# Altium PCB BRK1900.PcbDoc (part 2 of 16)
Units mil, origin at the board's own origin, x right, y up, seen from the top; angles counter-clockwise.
Board outline 8858.27 x 5905.51 mil, 10 copper layers (L1-TOP, L2-GND, L3-PWR, L4-GND, L5-PWR, L6-PWR, L7-GND, L8-SIG, L9-GND, L10-BOT), stack 48.824 mil thick; 456 components, 571 nets, 2296 pads, 2416 vias.
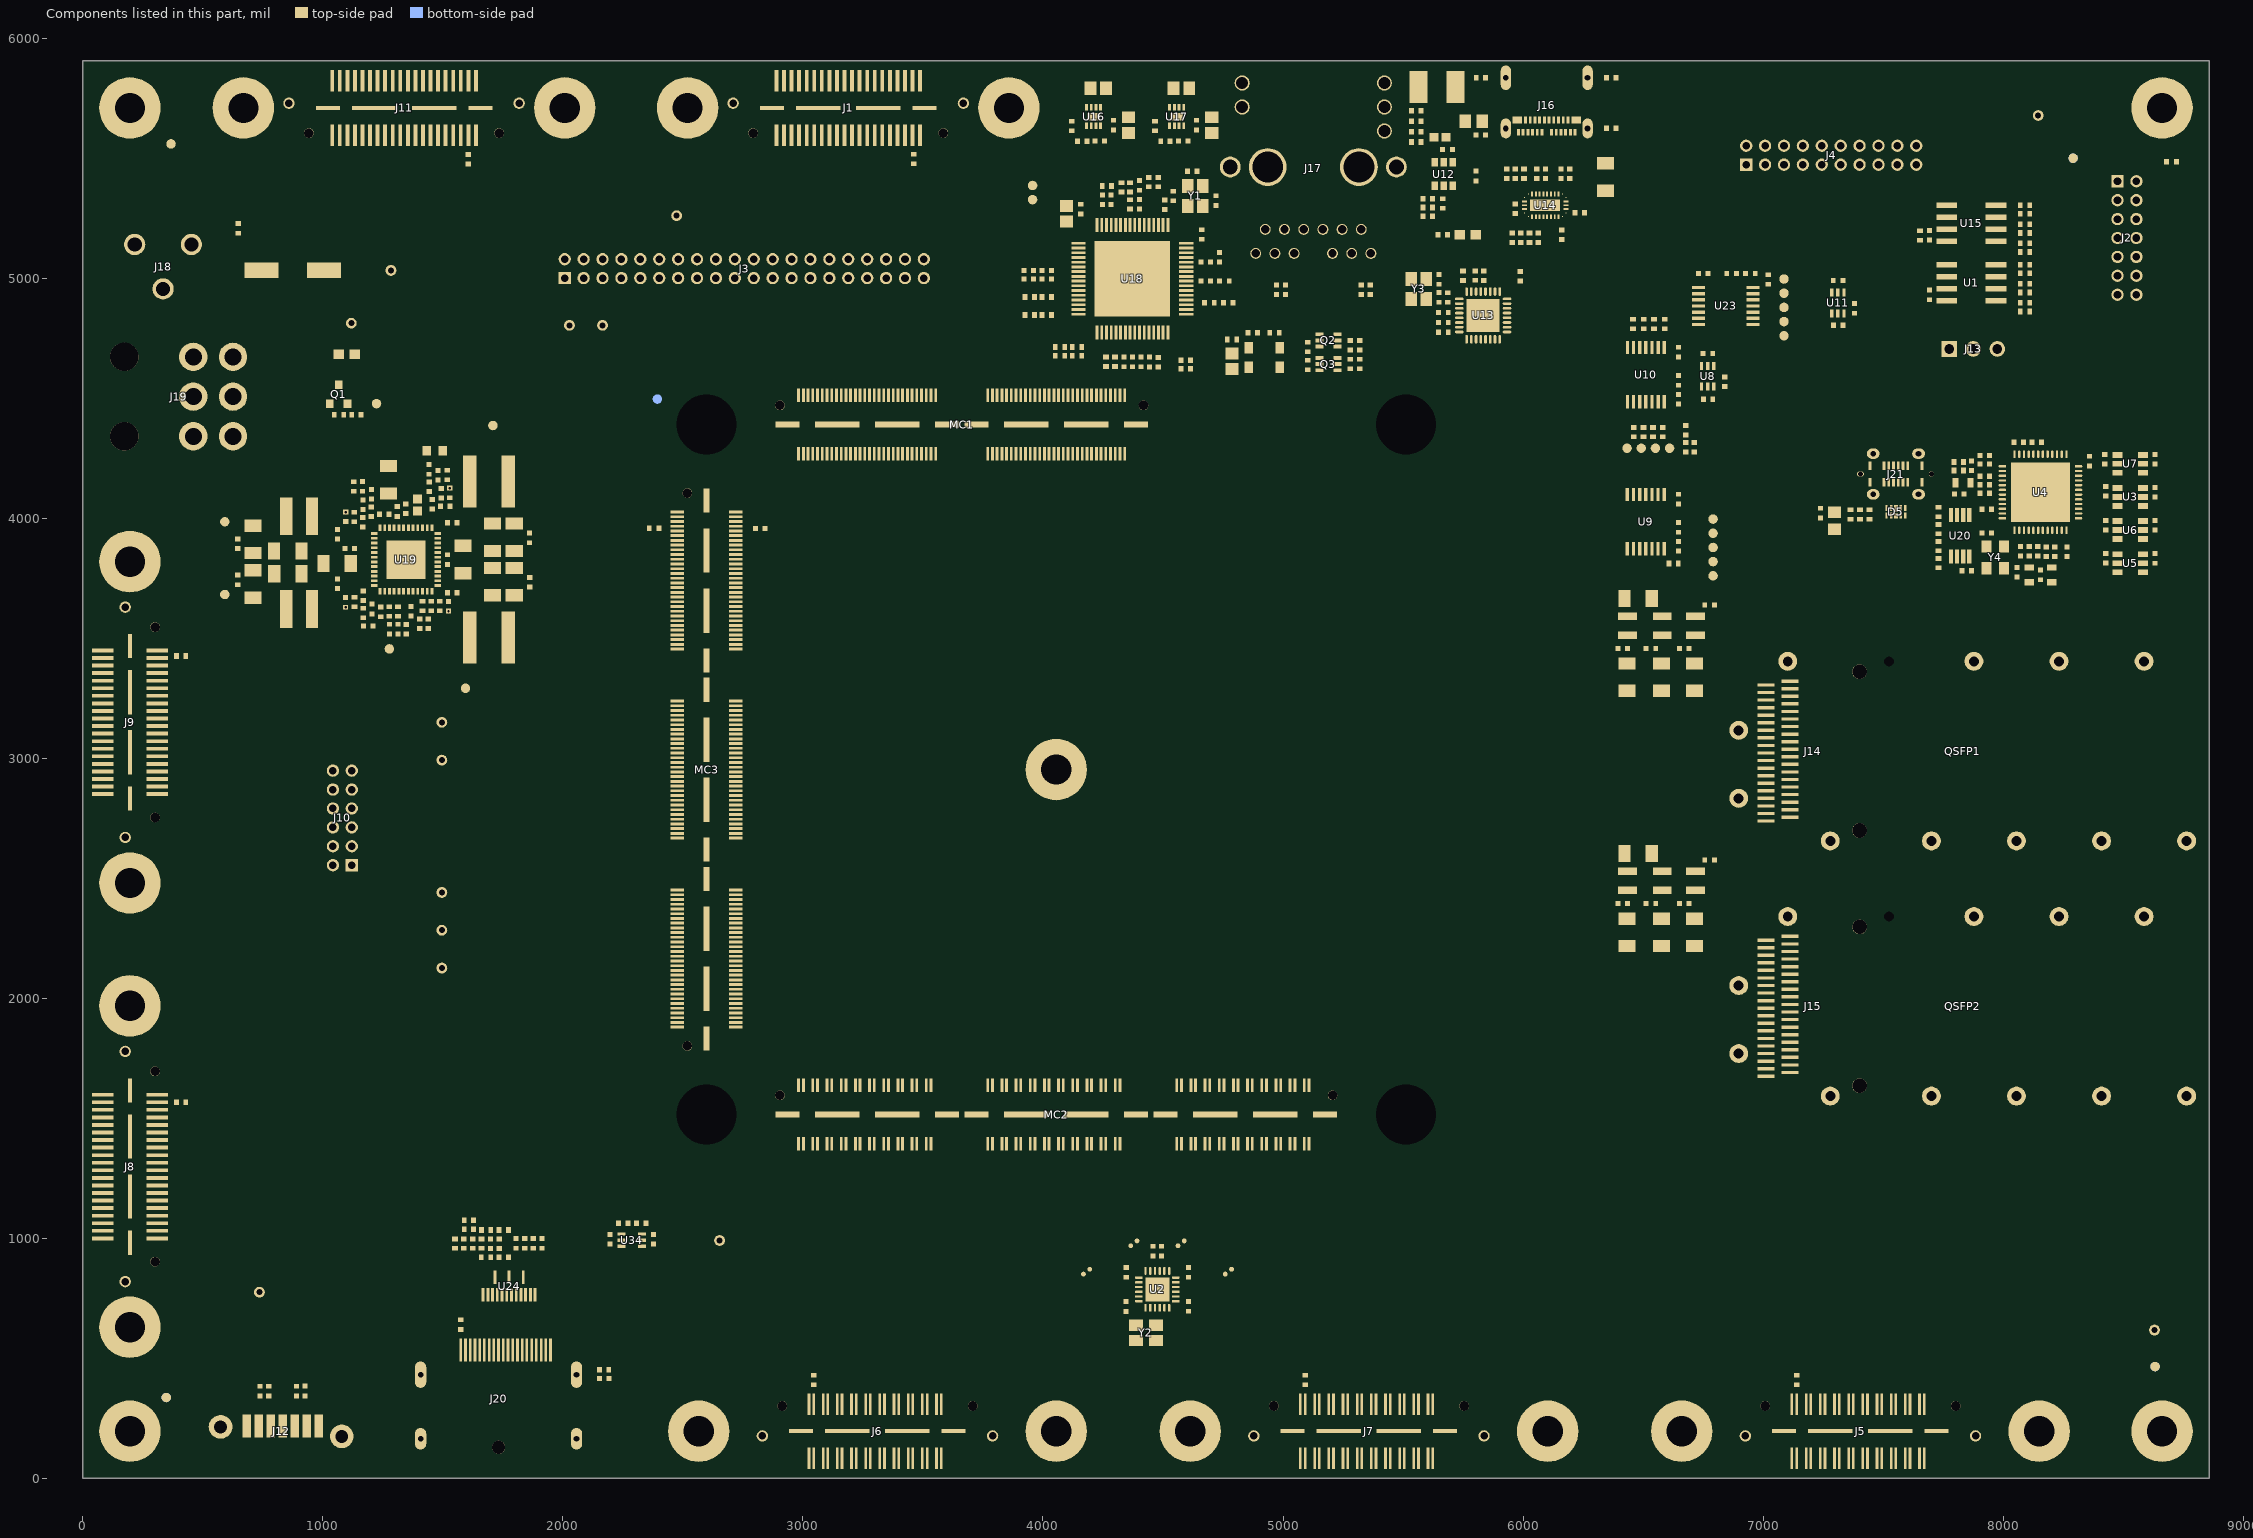
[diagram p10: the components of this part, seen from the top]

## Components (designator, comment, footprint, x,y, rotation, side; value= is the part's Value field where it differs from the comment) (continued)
R1 "CRCW040234K0FKED" RESC1005X06A#1 3462,5496 r90 top value="34 k"
R2 "CRCW040210K0FKED" RESC1005X06A#2 8091,4897 r0 top value="10.0 k"
R3 "CRCW040210K0FKED" RESC1005X06A#2 8091,4976 r0 top value="10.0 k"
R4 "CRCW040210K0FKED" RESC1005X06A#2 8091,5056 r0 top value="10.0 k"
R5 "CRCW040210K0FKED" RESC1005X06A#2 8091,4861 r180 top value="10.0 k"
R6 "CRCW040210K0FKED" RESC1005X06A#2 8091,4940 r180 top value="10.0 k"
R7 "CRCW040210K0FKED" RESC1005X06A#2 8091,5020 r180 top value="10.0 k"
R8 "RC0402FR-0714K3L" RESC1005X06A#1 7140.24,410 r270 top value="14.3 k"
R9 "CRCW040210K0FKED" RESC1005X06A#1 6712.6,4295.28 r90 top value="10.0 k"
R10 "SM-0402, 1%, 1/16W" RESC1005X06A#1 6677.17,4295.28 r270 top value=0
R11 "CRCW040210K0FKED" RESC1005X06A#1 6677.17,4366.14 r270 top value="10.0 k"
R12 "CRCW0402100KFKED" RESC1005X06A#1 5988.19,5007.87 r90 top value="100 k"
R13 "CRCW04025K10FKEDC" RESC1005X06A#1 7814.58,4198.44 r180 top value="5.1 k"
R14 "CRCW040224K9FKED" RESC1005X06A#1 3045,410 r270 top value="24.9 k"
R15 "CRCW040218K7FKED" RESC1005X06A#2 5093,410 r270 top value=18.7k
R16 "CRCW0402210KFKED" RESC1005X06A#1 410,1567 r180 top value="210 k"
R17 "CRCW040284K5FKED" RESC1005X06A#1 410,3426 r180 top value="84.5 k"
R18 "CRCW040249K9FKED" RESC1005X06A#1 1606,5495 r90 top value=49.9k
R19 "CRCW04025K10FKEDC" RESC1005X06A#1 7814.58,4233.87 r0 top value="5.1 k"
R20 "CRCW040212K0FKED" RESC1005X06A#1 8143.32,3862.22 r90 top value="12.0 k"
R21 "CRCW040210K0FKED" RESC1005X06A#1 8064.58,4316.55 r180 top value="10.0 k"
R22 "CRCW04020000Z0ED" RESC1005X06A#1 7363.79,4015.37 r270 top value=0
R23 "CRCW04020000Z0ED" RESC1005X06A#1 7403.16,4015.37 r270 top value=0
R24 "CRCW04020000Z0ED" RESC1005X06A#1 7442.53,4015.37 r270 top value=0
R25 "CRCW0402100KFKED" RESC1005X06A#1 7729.94,3883.48 r270 top value="100 k"
R26 "CRCW0402100KFKED" RESC1005X06A#1 7729.94,3812.61 r90 top value="100 k"
R27 "CRCW04022K00FKED" RESC1005X06A#1 7729.94,3954.35 r90 top value="2.0 k"
R28 "CRCW040210K0FKED" RESC1005X06A#1 7729.94,4025.21 r270 top value="10.0 k"
R41 "CRCW04024K75FKED" RESC1005X06A#1 6770.68,4495.95 r0 top value="4.75 k"
R42 "CRCW04024K75FKED" RESC1005X06A#1 6626.97,3811.02 r0 top value="4.75 k"
R43 "CRCW04024K75FKED" RESC1005X06A#1 6581.28,4358.36 r270 top value="4.75 k"
R44 "CRCW04024K75FKED" RESC1005X06A#2 6541.28,4358.36 r270 top value="4.75 k"
R45 "CRCW04024K75FKED" RESC1005X06A#1 6501.28,4358.36 r270 top value="4.75 k"
R46 "CRCW04024K75FKED" RESC1005X06A#2 6461.28,4358.36 r270 top value="4.75 k"
R47 "CRCW04024K75FKED" RESC1005X06A#2 6457.68,4809.06 r90 top value="4.75 k"
R48 "CRCW04024K75FKED" RESC1005X06A#1 6501.97,4809.06 r90 top value="4.75 k"
R49 "CRCW04024K75FKED" RESC1005X06A#1 6545.52,4809.06 r90 top value="4.75 k"
R50 "CRCW04024K75FKED" RESC1005X06A#1 6589.57,4809.06 r90 top value="4.75 k"
R51 "CRCW04024K75FKED" RESC1005X06A#1 7312.81,4803.67 r0 top value="4.75 k"
R52 "CRCW04024K75FKED" RESC1005X06A#1 7021.65,4994.09 r90 top value="4.75 k"
R58 "CRCW0402226KFKED" RESC1005X06A#1 4163.62,5570.09 r0 top value="226 k"
R59 "CRCW0402270KFKED" RESC1005X06A#1 4120.08,5633.46 r270 top value="270 k"
R60 "CRCW0402374KFKED" RESC1005X06A#1 4509.84,5570.47 r0 top value="374 k"
R61 "CRCW0402118KFKED" RESC1005X06A#1 4466.54,5633.46 r270 top value="118 k"
R62 "NoLoad" RESC1005X06A#1 3944.88,4921.26 r180 top
R63 "NoLoad" RESC1005X06A#1 3944.88,4846.46 r180 top
R64 "NoLoad" RESC1005X06A#1 4070.87,4712.6 r180 top
R65 "CRCW04022K00FKED" RESC1005X06A#1 5665,5180 r180 top value="2.0 k"
R66 "CRCW040215K0FKED" RESC1005X06A#1 5665.35,5311.02 r90 top value="15 k"
R67 "CRCW04020000Z0ED" RESC1005X06A#2 5603,5331 r0 top value=0
R68 "CRCW040210K0FKED" RESC1005X06A#2 5603,5294 r0 top value="10.0 k"
R69 "CRCW04021K00FKED" RESC1005X06A#1 5800.02,5010.28 r270 top value="1 k"
R70 "CRCW04020000Z0ED" RESC1005X06A#2 5603,5257 r0 top value=0
R71 "CRCW0402499KFKEDC" RESC1005X06A#1 5990.41,5168.32 r270 top value="499 k"
R72 "CRCW0402887KFKED" RESC1005X06A#1 6062.41,5168.32 r270 top value="887 k"
R73 "CRCW04020000Z0ED" RESC1005X06A#1 5954.41,5168.32 r270 top value=0
R74 "CRCW040210K0FKED" RESC1005X06A#1 6026.41,5168.32 r270 top value="10.0 k"
R75 "CRCW04021M00JNED" RESC1005X06A#1 5686.02,4919.28 r270 top value="1 M"
R76 "CRCW04028K06FKED" RESC1005X06A#1 5749.61,5009.41 r270 top value="8.06 k"
R77 "CRCW04020000Z0ED" RESC1005X06A#1 6367,5834 r0 top value=0
R78 "CRCW04020000Z0ED" RESC1005X06A#1 5824,5834 r180 top value=0
R79 "CRCW04020000Z0ED" RESC1005X06A#1 6367,5624 r0 top value=0
R80 "CRCW040210K0FKED" RESC1005X06A#1 5931.41,5434.32 r90 top value="10.0 k"
R81 "CRCW040210K0FKED" RESC1005X06A#1 5967.41,5434.32 r90 top value="10.0 k"
R82 "CRCW0402210KFKED" RESC1005X06A#1 6236.09,5272.32 r0 top value="210 k"
R83 "CRCW040210K0FKED" RESC1005X06A#1 6003.41,5434.32 r270 top value="10.0 k"
R84 "CRCW040210K0FKED" RESC1005X06A#1 8091,5145 r0 top value="10.0 k"
R85 "CRCW040210K0FKED" RESC1005X06A#1 8091,5224 r0 top value="10.0 k"
R86 "CRCW040210K0FKED" RESC1005X06A#1 8091,5304 r0 top value="10.0 k"
R87 "CRCW040210K0FKED" RESC1005X06A#1 8091,5109 r180 top value="10.0 k"
R88 "CRCW040210K0FKED" RESC1005X06A#1 8091,5188 r180 top value="10.0 k"
R89 "CRCW040210K0FKED" RESC1005X06A#1 8091,5268 r180 top value="10.0 k"
R90 "CRCW04022K20JNED" RESC1005X06A#2 4015.75,4921.26 r180 top value="2.2 k"
R91 "CRCW04022K20JNED" RESC1005X06A#2 4015.75,4846.46 r180 top value="2.2 k"
R92 "NoLoad" RESC1005X06A#2 4141.73,4712.6 r180 top
R93 "CRCW04020000Z0ED" RESC1005X06A#2 7653.54,5177.17 r90 top value=0
R94 "CRCW0402240RFKED" RESC1005X06A#2 5318.9,4720.47 r90 top value=240
R95 "CRCW04025K76FKEDC" RESC1005X06A#2 4299.83,4651.28 r270 top value="5.76 k"
R96 "CRCW04022K49FKED" RESC1005X06A#2 4262.72,4651.52 r90 top value="2.49 k"
R97 "CRCW04024K75FKED" RESC1005X06A#2 4362.2,5377.95 r270 top value="4.75 k"
R98 "CRCW0402240RFKED" RESC1005X06A#2 5279.53,4641.73 r90 top value=240
R99 "CRCW04024K75FKED" RESC1005X06A#2 4326.77,5377.95 r90 top value="4.75 k"
R100 "CRCW04024K75FKED" RESC1005X06A#2 4266.02,5383.29 r180 top value="4.75 k"
R101 "CRCW04024K75FKED" RESC1005X06A#2 4362.2,5307.09 r90 top value="4.75 k"
R102 "CRCW0402240RFKED" RESC1005X06A#2 5318.9,4641.73 r90 top value=240
R103 "CRCW040210K0FKED" RESC1005X06A#2 5102.36,4712.6 r90 top value="10.0 k"
R104 "CRCW040210K0FKED" RESC1005X06A#1 4070.87,4677.17 r180 top value="10.0 k"
R105 "CRCW04022K49FKED" RESC1005X06A#1 4141.73,4677.17 r180 top value="2.49 k"
R106 "CRCW040210K0FKED" RESC1005X06A#1 5279.53,4720.47 r90 top value="10.0 k"
R107 "CRCW04021M00JNED" RESC1005X06A#1 5555.12,5610.24 r180 top value="1 M"
R108 "CRCW04020000Z0ED" RESC1005X06A#2 5555.12,5653.54 r180 top value=0
R109 "CRCW04020000Z0ED" RESC1005X06A#2 5555.12,5566.93 r180 top value=0
R110 "CRCW04020000Z0ED" RESC1005X06A#2 5555.12,5696.85 r180 top value=0
R111 "CRCW04020000Z0ED" RESC1005X06A#2 4506.66,5305.32 r90 top value=0
R112 "CRCW040210K0FKED" RESC1005X06A#1 5102.36,4637.8 r270 top value="10.0 k"
R113 "CRCW04022K20JNED" RESC1005X06A#2 4874.02,4771.65 r180 top value="2.2 k"
R114 "CRCW04022K20JNED" RESC1005X06A#2 4480.31,4649.61 r270 top value="2.2 k"
R115 "CRCW04022K20JNED" RESC1005X06A#2 4440.94,5399.61 r90 top value="2.2 k"
R116 "CRCW04022K20JNED" RESC1005X06A#2 4480.31,5399.61 r90 top value="2.2 k"
R117 "CRCW04021M00JNED" RESC1005X06A#2 4543.31,5342.13 r90 top value="1 M"
R118 "CRCW040211K0FKED" RESC1005X06A#2 4661.42,5181.1 r270 top value="11.0 k"
R119 "CRCW04020000Z0ED" RESC1005X06A#2 4964.57,4771.65 r180 top value=0
R120 "CRCW040210K0FKED" RESC1005X06A#1 1313.29,3611.53 r270 top value="10.0 k"
R121 "CRCW040210K0FKED" RESC1005X06A#1 1129,4132 r90 top value="10.0 k"
R122 "SM-0402, 1%, 1/16W" RESC1005X06A#1 1487.58,3633.64 r270 top value="31.6 k"
R123 "SM-0402, 1%, 1/16W" RESC1005X06A#1 1451.58,3633.64 r90 top value="10.0 k"
R124 "CRCW040215K0FKED" RESC1005X06A#1 1415.58,3633.64 r270 top value="15 k"
R125 "SM-0402, 1%, 1/16W" RESC1005X06A#1 1494,4104 r90 top value="31.6 k"
R126 "SM-0402, 1%, 1/16W" RESC1005X06A#1 1510,4049 r180 top value="10.0 k"
R127 "CRCW040215K0FKED" RESC1005X06A#1 1443,4131 r90 top value="15 k"
R128 "CRCW040252K3FKED" RESC1005X06A#1 1131.2,4005.08 r90 top value="52.3 k"
R129 "CRCW040215K0FKED" RESC1005X06A#1 1202.58,4026.64 r90 top value="15 k"
R130 "SM-0402, 1%, 1/16W" RESC1005X06A#1 1166,3982.68 r270 top value="10.0 k"
R131 "CRCW040210K0FKED" RESC1005X06A#1 1277.29,3611.53 r270 top value="10.0 k"
R132 "CRCW040252K3FKED" RESC1005X06A#1 1132,3651 r270 top value="52.3 k"
R133 "CRCW040215K0FKED" RESC1005X06A#1 1169.29,3604.53 r270 top value="15 k"
R134 "CRCW0402374KFKED" RESC1005X06A#1 1348.4,3537.55 r90 top value="374 k"
R135 "SM-0402, 1%, 1/16W" RESC1005X06A#1 1169,3677 r90 top value="10.0 k"
R136 "CRCW06030000Z0EA" RESC1608N 1466,4280 r180 top value=0
R137 "CRCW040210K0JNED" RESC1005X06A#1 1518,4180 r270 top value="10 k"
R138 "CRCW04022K00FKED" RESC1005X06A#1 1140,4431 r180 top value="2.0 k"
R140 "CRCW040210K0FKED" RESC1005X06A#1 4787.4,4744.09 r0 top value="10.0 k"
R148 "CRCW040210K0FKED" RESC1005X06A#1 1068,4431 r0 top value="10.0 k"
R151 "CRCW04020000Z0ED" RESC1005X06A#1 2251.97,1063.39 r0 top value=0
R152 "CRCW04020000Z0ED" RESC1005X06A#1 2326.77,1063.39 r180 top value=0
R153 "CRCW040249R9FKEDC" RESC1005X06A#1 1753.53,1035 r180 top value=49.9
R154 "CRCW0402100KFKED" RESC1005X06A#1 1754.21,922 r180 top value="100 k"
R155 "CRCW04021M00FKEDC" RESC1005X06A#1 2172,453 r180 top value="1 M"
R156 "CRCW04021M00FKEDC" RESC1005X06A#1 1550.53,978 r90 top value="1 M"
R157 "CRCW04021M00FKEDC" RESC1005X06A#1 1587.53,978 r90 top value="1 M"
R158 "CRCW040249R9FKEDC" RESC1005X06A#1 1680.53,1035 r180 top value=49.9
R159 "CRCW0402100KFKED" RESC1005X06A#2 1624.53,978 r90 top value="100 k"
R167 "CRCW0402100KFKED" RESC1005X06A#1 1679.84,922 r180 top value="100 k"
R168 "CRCW04022K49FKED" RESC1005X06A#1 1608.53,1038 r180 top value="2.49 k"
R169 "CRCW04021K50FKED" RESC1005X06A#1 1608.53,1075 r0 top value="1.5 k"
R181 "CRCW040210R0FKED" RESC1005X06A#1 1661.53,978 r270 top value=10
R183 "CRCW04022K49FKED" RESC1005X06A#1 4594.49,4657.48 r0 top value="2.49 k"
R184 "CRCW04022K49FKED" RESC1005X06A#1 4594.49,4622.05 r180 top value="2.49 k"
TP1 "+1.8V" TP-PTH-25/45 2653,991 r90 top
TP2 "DGND" TP-PTH-25/45 8629.92,618.11 r0 top
TP3 "+3.3V" TP-PTH-25/45 2165.35,4803.15 r90 top
TP4 "VREF_67" TP-PTH-25/45 1496.06,2992.13 r90 top
TP5 "DGND" TP-PTH-25/45 736.22,775.59 r90 top
TP6 "VCCO_28" TP-PTH-25/45 2474,5260 r90 top
TP7 "VCCO_68" TP-PTH-25/45 1496.06,2440.94 r90 top
TP8 "DGND" TP-PTH-25/45 1284,5032 r180 top
TP9 "VREF_28" TP-PTH-25/45 2027.56,4803.15 r90 top
TP10 "VREF_68" TP-PTH-25/45 1496.06,2283.46 r90 top
TP11 "DGND" TP-PTH-25/45 8145.67,5677.17 r90 top
TP12 "VCCO_67" TP-PTH-25/45 1119,4812 r90 top
TP13 "VCCO_87_88" TP-PTH-25/45 1496.06,2125.98 r90 top
TP14 "VCC_PSBATT" TP-PTH-25/45 1496.06,3149.61 r90 top
TP15 "+3.3V_QSFP" TP-SMD40 1594.49,3291.34 r180 top
TP16 "+3.3V_AUX" TP-SMD40 1708.66,4385.83 r180 top
TP17 "+5V_AUX" TP-SMD40 592,3985 r90 top
TP18 "+5V_SZG" TP-SMD40 592,3682 r90 top
TP19 "TESTPOINT-SMD40" TP-SMD40 1277.29,3455.53 r0 top
TP22 "+1.1V_ETH" TP-SMD40 3956.69,5385.83 r180 top
TP23 "PGOOD" TP-SMD40 1224,4477 r270 top
TP24 "TESTPOINT-SMD20" TP-SMD20 4194.79,871.23 r90 top
TP25 "TESTPOINT-SMD20" TP-SMD20 4391.64,989.34 r90 top
TP26 "TESTPOINT-SMD20" TP-SMD20 4588.49,989.34 r90 top
TP27 "TESTPOINT-SMD20" TP-SMD20 4785.34,871.23 r90 top
TP28 "TESTPOINT-SMD20" TP-SMD20 4168.71,851.15 r90 top
TP29 "TESTPOINT-SMD20" TP-SMD20 4365.56,969.26 r90 top
TP30 "TESTPOINT-SMD20" TP-SMD20 4562.41,969.26 r90 top
TP31 "TESTPOINT-SMD20" TP-SMD20 4759.26,851.15 r90 top
TP32 "QSFP_1_INT_B_3V3" TP-SMD40 6791.34,3996.06 r270 top
TP33 "QSFP_1_MODPRS_B_3V3" TP-SMD40 6791.34,3937.01 r270 top
TP34 "QSFP_1_RESET_B_3V3" TP-SMD40 6791.34,3877.95 r270 top
TP35 "QSFP_1_MODSEL_B_3V3" TP-SMD40 6791.34,3818.9 r270 top
TP36 "QSFP_1_LP_MODE_3V3" TP-SMD40 6791.34,3759.84 r270 top
TP37 "QSFP2_SCL" TP-SMD40 6610.24,4291.34 r180 top
TP38 "QSFP2_SDA" TP-SMD40 6551.18,4291.34 r180 top
TP39 "QSFP1_SCL" TP-SMD40 6492.13,4291.34 r180 top
TP40 "QSFP1_SDA" TP-SMD40 6433.07,4291.34 r180 top
TP41 "QSFP_2_INT_B_3V3" TP-SMD40 7086.61,4759.84 r270 top
TP42 "QSFP_2_MODPRS_B_3V3" TP-SMD40 7086.61,4996.06 r270 top
TP43 "QSFP_2_RESET_B_3V3" TP-SMD40 7086.61,4937.01 r270 top
TP44 "QSFP_2_MODSEL_B_3V3" TP-SMD40 7086.61,4877.95 r270 top
TP45 "QSFP_2_LP_MODE_3V3" TP-SMD40 7086.61,4818.9 r270 top
TP46 "+2.5V_ETH" TP-SMD40 3956.69,5326.77 r180 top
U1 "24FC256-I/SN" SO-G8 7867,4981 r90 top
U2 "SI5338B-B-GM" Si5338 4476.38,787.4 r90 top
U3 "SN74AXC1T45DBVR" SOT23-6 8529.15,4088.2 r270 top
U4 "FT232HQ" FT232HQ 8155.13,4107.89 r90 top
U5 "SN74AXC1T45DBVR" SOT23-6 8529.15,3812.61 r270 top
U6 "SN74AXC1T45DBVR" SOT23-6 8529.15,3950.41 r270 top
U7 "SN74AXC1T45DBVR" SOT23-6 8529.15,4226 r270 top
U8 "SN74AXC1T45DCK" DCK-R-PDSO-G6 6768.9,4590.95 r180 top
U9 "MAX3378EEUD+" MAX3378EEUD+ 6511.01,3985.8 r180 top
U10 "MAX3378EEUD+" MAX3378EEUD+ 6511.28,4598 r180 top
U11 "SN74AXC1T45DCK" DCK-R-PDSO-G6 7311.02,4896.67 r180 top
U12 "AP22653AW6-7" AP2265XW6 5669.29,5433.07 r270 top
U13 "USB3320C-EZK" QFN-32 5833.55,4844.46 r90 top
U14 "HD3SS3220RNH" WQFN-30 6092.38,5303.24 r90 top
U15 "24AA025E48-I/SN" SO-G8 7867,5229 r90 top
U16 "MAX25300BATA/V+" MAX25300 4210.63,5672.83 r270 top
U17 "MAX25300BATA/V+" MAX25300 4557.09,5672.83 r270 top
U18 "DP83867IRPAP" DP83867IRPAP 4372.65,4997.28 r180 top
U19 "TPS65400RGZ" PVQFN-48 1346.58,3827.64 r180 top locked
U20 "93LC56B-E/MS-CFG001" MSOP-MS8_N 7820.49,3926.79 r270 top
U23 "MAX3378EEUD+" MAX3378EEUD+ 6843.93,4883.75 r270 top
U24 "TPD8S009DSMR" TPD8S009DSMR 1776.25,801.42 r0 top locked
U34 "SN74AXC1T45DCK" DCK-R-PDSO-G6 2287.4,992.52 r270 top
Y1 "ABM8-25.000MHZ-D2Y-T" OSC_SMD_32x25 4633.86,5342.13 r270 top
Y2 "FA-238 25.0000MB-C3" OSC_SMD_32x25 4429.13,606.3 r180 top
Y3 "T12BC1-19.200MHZ-T" OSC_SMD_32x25 5565.52,4955.01 r90 top
Y4 "ABM8-12.000MHZ-B2-T" ABM8 7966.16,3836.24 r270 top

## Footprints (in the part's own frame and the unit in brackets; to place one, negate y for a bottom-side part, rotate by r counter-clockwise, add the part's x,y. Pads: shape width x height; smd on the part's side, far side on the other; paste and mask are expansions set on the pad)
0455580003 [mm]
  round 3 hole 3 unplated: 0(-4.2,7.3) 0(4.2,7.3)
  round 3 hole 1.8: 1(-4.2,0) 2(0,0) 3(4.2,0) 4(-4.2,-4.2) 5(0,-4.2) 6(4.2,-4.2)
  silkscreen extent -7,1 7,11.12
0472720001 [mm]
  rect 0.28x2.4 smd: 1(5.5,10.28) 2(5,10.28) 3(4.5,10.28) 4(4,10.28) 5(3.5,10.28) 6(3,10.28) 7(2.5,10.28) 8(2,10.28) 9(1.5,10.28) 10(1,10.28) 11(0.5,10.28) 12(0,10.28) 13(-0.5,10.28) 14(-1,10.28) 15(-1.5,10.28) 16(-2,10.28) 17(-2.5,10.28) 18(-3,10.28) 19(-3.5,10.28) 20(-4,10.28)
  round 1.4 hole 1.4 unplated paste-2539.97 mask+0.076: M1(0,0)
  oval 1.2x2.8 hole 0.6 slot 2.2 at 90 deg paste-2539.97 mask+0.076: SHELL1(-8.25,7.68) SHELL2(8.25,7.68)
  oval 1.2x2.3 hole 0.6 slot 1.7 at 90 deg paste-2539.97 mask+0.076: SHELL3(8.25,0.9) SHELL4(-8.25,0.9)
  silkscreen extent -8.51,-2.73 8.5,10.2
1054500101 [mm]
  rect 0.3x0.7 smd: A1(1.32,0.41) A2(1.82,0.41) A3(2.32,0.41) A4(2.82,0.41) A5(3.32,0.41) A6(3.82,0.41) A7(4.82,0.41) A8(5.32,0.41) A9(5.82,0.41) A10(6.32,0.41) A11(6.82,0.41) A12(7.32,0.41) B2(6.57,-0.89) B3(6.07,-0.89) B4(5.57,-0.89) B5(5.07,-0.89) B6(4.57,-0.89) B7(4.07,-0.89) B8(3.57,-0.89) B9(3.07,-0.89) B10(2.57,-0.89) B11(2.07,-0.89)
  rect 1x0.7 smd: B1(7.42,-0.89) B12(1.22,-0.89)
  oval 1.1x2.1 hole 0.6 slot 1.6 at 90 deg: M1(0,0) M2(8.64,0)
  oval 1.1x2.6 hole 0.6 slot 2.1 at 90 deg: M3(8.64,-5.36) M4(0,-5.36)
  silkscreen extent -0.18,-3.7 8.82,-1.4
ABM8 [mm]
  rect 1.3x1.05 smd: 1(-1.15,-0.925) 2(1.15,-0.925) 3(1.15,0.925) 4(-1.15,0.925)
  silkscreen extent -1.98,-0.14 1.98,0.14
AP2265XW6 [mm]
  rect 0.9x0.7 smd: 1(-1.25,0.95) 2(-1.25,0) 3(-1.25,-0.95) 4(1.25,-0.95) 5(1.25,0) 6(1.25,0.95)
  silkscreen extent -0.54,-1.55 0.54,1.55
CAPAE9083X70N [mm] "Aluminum Electrolytic Capacitor, Body 8.30x8.30x7.00mm, IPC Medium Density"
  rect 3.6x1.65 smd: 1(-3.325,0) 2(3.325,0)
  silkscreen extent -4.25,-4.25 4.25,4.25
CAPC1005X06A#1 [mm] "Chip Capacitor, 2-Leads, Body 1.00x0.50mm, OK custom footprint"
  rect 0.52x0.55 smd mask+0.051: 1(-0.51,0) 2(0.51,0)
CAPC1005X06A#2 [mm] "Chip Capacitor, 2-Leads, Body 1.00x0.50mm, OK custom footprint"
  rect 0.52x0.55 smd: 1(-0.51,0) 2(0.51,0)
CAPC1608X09N [mm] "Chip Capacitor, 2-Leads, Body 1.60x0.80mm, IPC Medium Density"
  rect 0.95x0.95 smd: 1(-0.625,0) 2(0.625,0)
  body extent -0.85,-0.45 0.85,0.45, height 0.9
CAPC2012X14N [mm] "Chip Capacitor, 2-Leads, Body 2.00x1.25mm, IPC Medium Density"
  rect 1.25x1.4 smd: 1(-0.825,0) 2(0.825,0)
  body extent -1.05,-0.67 1.05,0.67, height 1.4
CAPC3216N [mm] "Chip Capacitor, Body 3.2x1.6mm, IPC Medium Density"
  rect 1.3x1.8 smd: 1(-1.45,0) 2(1.45,0)
  silkscreen extent -0.54,-1.08 0.54,1.08, body extent -1.7,-0.9 1.7,0.9, height 1.35
CC4532-1812 [mm] "Chip Capacitor; Body 4.5 x 3.2 mm (LxW typ)"
  rect 1.9x3.4 smd: 1(-1.95,0) 2(1.95,0)
  silkscreen extent -0.74,-1.85 0.74,1.85
CD1608-0603-PIN1-CATHODE [mm] "Chip Diode; Body 1.6 x 0.8 mm (LxW typ)"
  rect 1.1x1 smd: 1(-0.85,0) 2(0.85,0)
CIGT252010 [mm]
  rect 0.8x2 smd: 1(-1,0) 2(1,0)
CUI-PJ102A [mm] "2.1mm/5.5mm DC power jack"
  round 2.25 hole 1.5: 1(0,13.7) 2(0,7.7) 3(4.7,10.7)
  silkscreen extent -4.5,2.8 4.51,14.5
D5V0FS4U10LP [mm]
  rect 0.25x0.625 smd mask+0.025: 1(-1,-0.387) 2(-0.5,-0.387) 4(0.5,-0.387) 5(1,-0.387) 6(1,0.387) 7(0.5,0.387) 9(-0.5,0.387) 10(-1,0.387)
  rect 0.45x0.7 smd mask+0.025: 3(0,-0.35)
  rect 0.45x0.575 smd mask+0.025: 8(0,0.413)
DCK-R-PDSO-G6 [mm]
  rect 0.35x0.85 smd: 1(-0.65,-1.1) 2(0,-1.1) 3(0.65,-1.1) 4(0.65,1.1) 5(0,1.1) 6(-0.65,1.1)
  silkscreen extent -1.01,-0.41 1.01,0.41
DP83867IRPAP [mm]
  rect 1.5x0.3 smd: 1(-5.7,3.75) 2(-5.7,3.25) 3(-5.7,2.75) 4(-5.7,2.25) 5(-5.7,1.75) 6(-5.7,1.25) 7(-5.7,0.75) 8(-5.7,0.25) 9(-5.7,-0.25) 10(-5.7,-0.75) 11(-5.7,-1.25) 12(-5.7,-1.75) 13(-5.7,-2.25) 14(-5.7,-2.75) 15(-5.7,-3.25) 16(-5.7,-3.75) 33(5.7,-3.75) 34(5.7,-3.25) 35(5.7,-2.75) 36(5.7,-2.25) 37(5.7,-1.75) 38(5.7,-1.25) 39(5.7,-0.75) 40(5.7,-0.25) 41(5.7,0.25) 42(5.7,0.75) 43(5.7,1.25) 44(5.7,1.75) 45(5.7,2.25) 46(5.7,2.75) 47(5.7,3.25) 48(5.7,3.75)
  rect 0.3x1.5 smd: 17(-3.75,-5.7) 18(-3.25,-5.7) 19(-2.75,-5.7) 20(-2.25,-5.7) 21(-1.75,-5.7) 22(-1.25,-5.7) 23(-0.75,-5.7) 24(-0.25,-5.7) 25(0.25,-5.7) 26(0.75,-5.7) 27(1.25,-5.7) 28(1.75,-5.7) 29(2.25,-5.7) 30(2.75,-5.7) 31(3.25,-5.7) 32(3.75,-5.7) 49(3.75,5.7) 50(3.25,5.7) 51(2.75,5.7) 52(2.25,5.7) 53(1.75,5.7) 54(1.25,5.7) 55(0.75,5.7) 56(0.25,5.7) 57(-0.25,5.7) 58(-0.75,5.7) 59(-1.25,5.7) 60(-1.75,5.7) 61(-2.25,5.7) 62(-2.75,5.7) 63(-3.25,5.7) 64(-3.75,5.7)
  rect 8x8 smd paste-10 mask-10: PAD(0,0)
  silkscreen extent -6.22,-5.15 5.15,6.22
FID1MM/2MM-SS [mm] "Fiducial 1mm copper, 2mm soldermask, single-side"
  round 1 smd paste-0.5 mask+0.5: FID?(0,0)
FT232HQ [mm]
  rrect100% 0.8x0.25 smd: 1(-4.025,2.75) 2(-4.025,2.25) 3(-4.025,1.75) 4(-4.025,1.25) 5(-4.025,0.75) 6(-4.025,0.25) 7(-4.025,-0.25) 8(-4.025,-0.75) 9(-4.025,-1.25) 10(-4.025,-1.75) 11(-4.025,-2.25) 12(-4.025,-2.75) 25(4.025,-2.75) 26(4.025,-2.25) 27(4.025,-1.75) 28(4.025,-1.25) 29(4.025,-0.75) 30(4.025,-0.25) 31(4.025,0.25) 32(4.025,0.75) 33(4.025,1.25) 34(4.025,1.75) 35(4.025,2.25) 36(4.025,2.75)
  rrect100% 0.25x0.8 smd: 13(-2.75,-4.025) 14(-2.25,-4.025) 15(-1.75,-4.025) 16(-1.25,-4.025) 17(-0.75,-4.025) 18(-0.25,-4.025) 19(0.25,-4.025) 20(0.75,-4.025) 21(1.25,-4.025) 22(1.75,-4.025) 23(2.25,-4.025) 24(2.75,-4.025) 37(2.75,4.025) 38(2.25,4.025) 39(1.75,4.025) 40(1.25,4.025) 41(0.75,4.025) 42(0.25,4.025) 43(-0.25,4.025) 44(-0.75,4.025) 45(-1.25,4.025) 46(-1.75,4.025) 47(-2.25,4.025) 48(-2.75,4.025)
  rect 6.29x6.29 smd paste-10: PAD(0,0)
  silkscreen extent -4.51,-4.06 4.06,4.51
HDR1X3 [mil] ".1\" 1x3 Header"
  rect 65x65 hole 40: 1(0,0)
  round 65 hole 40: 2(100,0) 3(200,0)
  silkscreen extent -50,-50 250,50
HDR2X6-2MM [mm]
  rect 1.3x1.3 hole 0.8: 1(-5,-1)
  round 1.3 hole 0.8: 2(-5,1) 3(-3,-1) 4(-3,1) 5(-1,-1) 6(-1,1) 7(1,-1) 8(1,1) 9(3,-1) 10(3,1) 11(5,-1) 12(5,1)
  silkscreen extent -6,-2 6,2
HDR2X10-2MM [mm] "2mm 2x10 header"
  rect 1.3x1.3 hole 0.8: 1(-9,-1)
  round 1.3 hole 0.8: 2(-9,1) 3(-7,-1) 4(-7,1) 5(-5,-1) 6(-5,1) 7(-3,-1) 8(-3,1) 9(-1,-1) 10(-1,1) 11(1,-1) 12(1,1) 13(3,-1) 14(3,1) 15(5,-1) 16(5,1) 17(7,-1) 18(7,1) 19(9,-1) 20(9,1)
  silkscreen extent -10,-2 10,2
HDR2X20-2MM [mm] "2mm 2x20 header"
  rect 1.3x1.3 hole 0.8: 1(-19,-1)
  round 1.3 hole 0.8: 2(-19,1) 3(-17,-1) 4(-17,1) 5(-15,-1) 6(-15,1) 7(-13,-1) 8(-13,1) 9(-11,-1) 10(-11,1) 11(-9,-1) 12(-9,1) 13(-7,-1) 14(-7,1) 15(-5,-1) 16(-5,1) 17(-3,-1) 18(-3,1) 19(-1,-1) 20(-1,1) 21(1,-1) 22(1,1) 23(3,-1) 24(3,1) 25(5,-1) 26(5,1) 27(7,-1) 28(7,1) 29(9,-1) 30(9,1) 31(11,-1) 32(11,1) 33(13,-1) 34(13,1) 35(15,-1) 36(15,1) 37(17,-1) 38(17,1) 39(19,-1) 40(19,1)
  silkscreen extent -20,-2 20,2
INDC1608X06N [mm] "Chip Inductor, 2-Leads, Body 1.60x0.80mm, IPC Medium Density"
  rect 0.65x0.98 smd: 1(-0.78,0) 2(0.78,0)
  silkscreen extent -0.19,-0.69 0.19,-0.69, body extent -0.88,-0.48 0.87,0.47, height 0.6
JSO-0515-01 [mil]
  round 0 hole 250 unplated: 1(0,0)
  Keep-Out Layer region: 0,-157.48 -60.27,-145.49 -111.36,-111.36 -145.49,-60.27 -157.48,0 -157.48,0 -145.49,60.27 -111.36,111.36 -60.27,145.49 0,157.48 0,157.48 60.27,145.49 111.36,111.36 145.49,60.27 157.48,0 157.48,0 145.49,-60.27 111.36,-111.36 60.27,-145.49 0,-157.48
L829-1J1T-43 [mm] "Ethernet MagJack"
  round 1.15 hole 0.89: 1(5.08,6.604) 2(3.048,6.604) 3(1.016,6.604) 4(-1.016,6.604) 5(-3.048,6.604) 6(-5.08,6.604) 7(6.096,9.144) 8(4.064,9.144) 9(2.032,9.144) 10(-2.032,9.144) 11(-4.064,9.144) 12(-6.096,9.144)
  round 1.6 hole 1.27: 13(7.52,-6.35) 14(7.52,-8.89) 15(-7.52,-3.81) 16(-7.52,-6.35) 17(-7.52,-8.89)
  round 2.2 hole 1.575: S1(-8.79,0) S2(8.79,0)
  round 4 hole 3.251: T1(-4.825,0) T2(4.825,0)
  silkscreen extent -8.9,-10.68 8.9,10.9
MAX3378EEUD+ [mm]
  rect 0.35x1.4 smd: 1(-1.95,-2.875) 2(-1.3,-2.875) 3(-0.65,-2.875) 4(0,-2.875) 5(0.65,-2.875) 6(1.3,-2.875) 7(1.95,-2.875) 8(1.95,2.875) 9(1.3,2.875) 10(0.65,2.875) 11(0,2.875) 12(-0.65,2.875) 13(-1.3,2.875) 14(-1.95,2.875)
  silkscreen extent -2.55,-2.26 2.55,2.27
MAX25300 [mm]
  rect 0.7x0.3 smd: 1(-0.99,0.75) 2(-0.99,0.25) 3(-0.99,-0.25) 4(-0.99,-0.75) 5(0.99,-0.75) 6(0.99,-0.25) 7(0.99,0.25) 8(0.99,0.75)
  rect 0.8x1.38 smd paste-10: EP(0,0)
  silkscreen extent -0.38,-1.15 0.38,1.15
MOLEX-67800-5005 [mm]
  rect 0.9x2.4 smd: 1(3.955,0.55) 2(2.685,0.55) 3(1.415,0.55) 4(0.145,0.55) 5(-1.125,0.55) 6(-2.395,0.55) 7(-3.665,0.55)
  round 2.5 hole 1.35: MH(-6.415,0.45) MH(6.415,-0.55)
  silkscreen extent -8.65,-3.9 8.6,2.85
MSOP-MS8_N [mm] "TSOP, 8-Leads, Body 3x3mm, Pitch 0.65mm, IPC Medium Density"
  rect 1.45x0.45 smd mask+0.051: 1(-2.2,0.975) 2(-2.2,0.325) 3(-2.2,-0.325) 4(-2.2,-0.975) 5(2.2,-0.975) 6(2.2,-0.325) 7(2.2,0.325) 8(2.2,0.975)
  silkscreen extent -1.52,-1.57 1.52,1.57, body extent -1.55,-1.55 1.55,1.55, height 1.1
MTG-3.2/6.5-PTH [mm] "Mounting hole, 3.2mm ID, 6.5mm OD, plated"
  round 6.5 hole 3.2: 1(0,0)
okLogo-23x5-2021 [mil] "Opal Kelly silkscreen logo (23mm x 5mm) - 2021 update"
  silkscreen extent -4,-15 672,100
OSC_SMD_32x25 [mm] "3.2x2.5mm SMD clock oscillator"
  rect 1.5x1.2 smd: 1(-1.06,-0.8) 2(1.06,-0.8) 3(1.06,0.8) 4(-1.06,0.8)
PVQFN-48 [mm]
  rect 0.7x0.3 smd mask+0.051: 1(-3.35,2.75) 2(-3.35,2.25) 3(-3.35,1.75) 4(-3.35,1.25) 5(-3.35,0.75) 6(-3.35,0.25) 7(-3.35,-0.25) 8(-3.35,-0.75) 9(-3.35,-1.25) 10(-3.35,-1.75) 11(-3.35,-2.25) 12(-3.35,-2.75) 25(3.35,-2.75) 26(3.35,-2.25) 27(3.35,-1.75) 28(3.35,-1.25) 29(3.35,-0.75) 30(3.35,-0.25) 31(3.35,0.25) 32(3.35,0.75) 33(3.35,1.25) 34(3.35,1.75) 35(3.35,2.25) 36(3.35,2.75)
  rect 0.3x0.7 smd mask+0.051: 13(-2.75,-3.35) 14(-2.25,-3.35) 15(-1.75,-3.35) 16(-1.25,-3.35) 17(-0.75,-3.35) 18(-0.25,-3.35) 19(0.25,-3.35) 20(0.75,-3.35) 21(1.25,-3.35) 22(1.75,-3.35) 23(2.25,-3.35) 24(2.75,-3.35) 37(2.75,3.35) 38(2.25,3.35) 39(1.75,3.35) 40(1.25,3.35) 41(0.75,3.35) 42(0.25,3.35) 43(-0.25,3.35) 44(-0.75,3.35) 45(-1.25,3.35) 46(-1.75,3.35) 47(-2.25,3.35) 48(-2.75,3.35)
  rect 4.08x4.08 smd mask+0.051: PAD(0,0)
  silkscreen extent -3.87,-3.6 3.6,3.87
QFN-32 [mm] "5x5mm QFN-32 (Modified QFN50P500X500-32V6M)"
  rect 3.5x3.5 smd: 0(0,0)
  oval 0.91x0.28 smd: 1(-2.525,1.75) 2(-2.525,1.25) 3(-2.525,0.75) 4(-2.525,0.25) 5(-2.525,-0.25) 6(-2.525,-0.75) 7(-2.525,-1.25) 8(-2.525,-1.75) 17(2.525,-1.75) 18(2.525,-1.25) 19(2.525,-0.75) 20(2.525,-0.25) 21(2.525,0.25) 22(2.525,0.75) 23(2.525,1.25) 24(2.525,1.75)
  oval 0.28x0.91 smd: 9(-1.75,-2.525) 10(-1.25,-2.525) 11(-0.75,-2.525) 12(-0.25,-2.525) 13(0.25,-2.525) 14(0.75,-2.525) 15(1.25,-2.525) 16(1.75,-2.525) 25(1.75,2.525) 26(1.25,2.525) 27(0.75,2.525) 28(0.25,2.525) 29(-0.25,2.525) 30(-0.75,2.525) 31(-1.25,2.525) 32(-1.75,2.525)
  silkscreen extent -3.18,-2.52 2.52,3.18
QSE-020-01-X-D-A-L-SYZYGY [mil]
  rect 100x17 smd paste+0: 0(-317.45,0) 0(317.55,0)
  rect 185x17 smd paste+0: 0(-124.95,0) 0(125.05,0)
  round 255.91 hole 125.98: 1(-669.24,0) 1(669.34,0)
  rect 16x89.5 smd paste+0: 1(-299.25,-112.8) 2(-299.25,112.8) 3(-267.75,-112.8) 4(-267.75,112.8) 5(-236.25,-112.8) 6(-236.25,112.8) 7(-204.75,-112.8) 8(-204.75,112.8) 9(-173.25,-112.8) 10(-173.25,112.8) 11(-141.75,-112.8) 12(-141.75,112.8) 13(-110.25,-112.8) 14(-110.25,112.8) 15(-78.75,-112.8) 16(-78.75,112.8) 17(-47.25,-112.8) 18(-47.25,112.8) 19(-15.75,-112.8) 20(-15.75,112.8) 21(15.75,-112.8) 22(15.75,112.8) 23(47.25,-112.8) 24(47.25,112.8) 25(78.75,-112.8) 26(78.75,112.8) 27(110.25,-112.8) 28(110.25,112.8) 29(141.75,-112.8) 30(141.75,112.8) 31(173.25,-112.8) 32(173.25,112.8) 33(204.75,-112.8) 34(204.75,112.8) 35(236.25,-112.8) 36(236.25,112.8) 37(267.75,-112.8) 38(267.75,112.8) 39(299.25,-112.8) 40(299.25,112.8)
  round 47.24 hole 31.5 paste-99999: MH(-479.48,-19.69) MH(479.58,-19.69)
  round 40.16 hole 40.16 unplated paste-99999: MH(-396.25,105) MH(396.35,105)
  silkscreen extent -886,-157 885,276
QSFP28_RECEPTACLE_SFF-8679 [mm]
  rect 0.35x1.8 smd: 1(1.4,7.37) 2(2.2,7.37) 3(3,7.37) 4(3.8,7.37) 5(4.6,7.37) 6(5.4,7.37) 7(6.2,7.37) 8(7,7.37) 9(7.8,7.37) 10(8.6,7.37) 11(9.4,7.37) 12(10.2,7.37) 13(11,7.37) 14(11.8,7.37) 15(12.6,7.37) 16(13.4,7.37) 17(14.2,7.37) 18(15,7.37) 19(15.8,7.37) 20(15.4,9.88) 21(14.6,9.88) 22(13.8,9.88) 23(13,9.88) 24(12.2,9.88) 25(11.4,9.88) 26(10.6,9.88) 27(9.8,9.88) 28(9,9.88) 29(8.2,9.88) 30(7.4,9.88) 31(6.6,9.88) 32(5.8,9.88) 33(5,9.88) 34(4.2,9.88) 35(3.4,9.88) 36(2.6,9.88) 37(1.8,9.88) 38(1,9.88)
  round 1.55 hole 1.55 unplated: MH(0,0) MH(16.8,0)
  L1-TOP keep-out region: -0.5,-3.16 0.5,-3.16 0.5,-2.16 -0.5,-2.16
  L1-TOP keep-out region: 16.3,-3.16 17.3,-3.16 17.3,-2.16 16.3,-2.16
  silkscreen extent -0.8,-3 17.6,9.7
QSFP28_SINGLE_CAGE [mm]
  round 2 hole 1.05: 0(-1.1,3.1) 0(-1.1,-7.6) 0(-1.1,-16.6) 0(-1.1,-25.6) 0(-1.1,-34.6) 0(3.4,12.79) 0(10.6,12.79) 0(17.9,-21.1) 0(17.9,-12.1) 0(17.9,7.6) 0(17.9,-30.1)
  round 0 hole 1.05 unplated: 0(17.9,-3.1)
  L1-TOP keep-out region: -2.7,13.5 -2.7,-37 19.5,-37 19.5,13.5 16.5,13.5 16.5,11.1 18,11.1 18,-1.6 15.9,-1.6 15.9,-3.5 0.9,-3.5 0.9,-1.6 -1.2,-1.6 -1.2,11.1 0.3,11.1 0.3,13.5
  silkscreen extent -1.1,-36.43 17.9,12.9
QSH-020-01-X-D-DP-A-L-SYZYGY [mm]
  rect 2.54x0.43 smd mask+0.051: 0(-8.07,0) 0(8.06,0)
  rect 4.7x0.43 smd mask+0.051: 0(-3.18,0) 0(3.17,0)
  round 6.5 hole 3.2: 1(-18.909,0) 1(18.911,0)
  rect 0.28x2.27 smd mask+0.051: 1(-7.25,-2.87) 2(-7.25,2.87) 3(-6.75,-2.87) 4(-6.75,2.87) 5(-5.75,-2.87) 6(-5.75,2.87) 7(-5.25,-2.87) 8(-5.25,2.87) 9(-4.25,-2.87) 10(-4.25,2.87) 11(-3.75,-2.87) 12(-3.75,2.87) 13(-2.75,-2.87) 14(-2.75,2.87) 15(-2.25,-2.87) 16(-2.25,2.87) 17(-1.25,-2.87) 18(-1.25,2.87) 19(-0.75,-2.87) 20(-0.75,2.87) 21(0.25,-2.87) 22(0.25,2.87) 23(0.75,-2.87) 24(0.75,2.87) 25(1.75,-2.87) 26(1.75,2.87) 27(2.25,-2.87) 28(2.25,2.87) 29(3.25,-2.87) 30(3.25,2.87) 31(3.75,-2.87) 32(3.75,2.87) 33(4.75,-2.87) 34(4.75,2.87) 35(5.25,-2.87) 36(5.25,2.87) 37(6.25,-2.87) 38(6.25,2.87) 39(6.75,-2.87) 40(6.75,2.87)
  round 1.2 hole 0.8 paste-2539.97 mask+0.076: MH(-12.18,-0.5) MH(12.18,-0.5)
  round 1.02 hole 1.02 unplated paste-2539.97: MH(-10.07,2.67) MH(10.07,2.67)
  silkscreen extent -25,-3.99 25,7.01
QTH-060-01-X-D [mm]
  rect 2.54x0.64 smd: 0(-18.445,0) 0(-1.555,0) 0(1.555,0) 0(18.445,0)
  rect 4.7x0.64 smd: 0(-13.175,0) 0(-6.825,0) 0(6.825,0) 0(13.175,0)
  rect 0.3x1.45 smd: 1(-17.25,3.09) 2(-17.25,-3.09) 3(-16.75,3.09) 4(-16.75,-3.09) 5(-16.25,3.09) 6(-16.25,-3.09) 7(-15.75,3.09) 8(-15.75,-3.09) 9(-15.25,3.09) 10(-15.25,-3.09) 11(-14.75,3.09) 12(-14.75,-3.09) 13(-14.25,3.09) 14(-14.25,-3.09) 15(-13.75,3.09) 16(-13.75,-3.09) 17(-13.25,3.09) 18(-13.25,-3.09) 19(-12.75,3.09) 20(-12.75,-3.09) 21(-12.25,3.09) 22(-12.25,-3.09) 23(-11.75,3.09) 24(-11.75,-3.09) 25(-11.25,3.09) 26(-11.25,-3.09) 27(-10.75,3.09) 28(-10.75,-3.09) 29(-10.25,3.09) 30(-10.25,-3.09) 31(-9.75,3.09) 32(-9.75,-3.09) 33(-9.25,3.09) 34(-9.25,-3.09) 35(-8.75,3.09) 36(-8.75,-3.09) 37(-8.25,3.09) 38(-8.25,-3.09) 39(-7.75,3.09) 40(-7.75,-3.09) 41(-7.25,3.09) 42(-7.25,-3.09) 43(-6.75,3.09) 44(-6.75,-3.09) 45(-6.25,3.09) 46(-6.25,-3.09) 47(-5.75,3.09) 48(-5.75,-3.09) 49(-5.25,3.09) 50(-5.25,-3.09) 51(-4.75,3.09) 52(-4.75,-3.09) 53(-4.25,3.09) 54(-4.25,-3.09) 55(-3.75,3.09) 56(-3.75,-3.09) 57(-3.25,3.09) 58(-3.25,-3.09) 59(-2.75,3.09) 60(-2.75,-3.09) 61(2.75,3.09) 62(2.75,-3.09) 63(3.25,3.09) 64(3.25,-3.09) 65(3.75,3.09) 66(3.75,-3.09) 67(4.25,3.09) 68(4.25,-3.09) 69(4.75,3.09) 70(4.75,-3.09) 71(5.25,3.09) 72(5.25,-3.09) 73(5.75,3.09) 74(5.75,-3.09) 75(6.25,3.09) 76(6.25,-3.09) 77(6.75,3.09) 78(6.75,-3.09) 79(7.25,3.09) 80(7.25,-3.09) 81(7.75,3.09) 82(7.75,-3.09) 83(8.25,3.09) 84(8.25,-3.09) 85(8.75,3.09) 86(8.75,-3.09) 87(9.25,3.09) 88(9.25,-3.09) 89(9.75,3.09) 90(9.75,-3.09) 91(10.25,3.09) 92(10.25,-3.09) 93(10.75,3.09) 94(10.75,-3.09) 95(11.25,3.09) 96(11.25,-3.09) 97(11.75,3.09) 98(11.75,-3.09) 99(12.25,3.09) 100(12.25,-3.09) 101(12.75,3.09) 102(12.75,-3.09) 103(13.25,3.09) 104(13.25,-3.09) 105(13.75,3.09) 106(13.75,-3.09) 107(14.25,3.09) 108(14.25,-3.09) 109(14.75,3.09) 110(14.75,-3.09) 111(15.25,3.09) 112(15.25,-3.09) 113(15.75,3.09) 114(15.75,-3.09) 115(16.25,3.09) 116(16.25,-3.09) 117(16.75,3.09) 118(16.75,-3.09) 119(17.25,3.09) 120(17.25,-3.09)
  round 1.02 hole 1.02 unplated: MH(-19.24,2.03) MH(19.24,2.03)
  silkscreen extent -20.05,-3.05 20.05,3.05
QTH-060-01-X-D-DP-A [mm]
  rect 2.54x0.64 smd: 0(-28.445,0) 0(-11.555,0) 0(-8.445,0) 0(8.445,0) 0(11.555,0) 0(28.445,0)
  rect 4.7x0.64 smd: 0(-23.175,0) 0(-16.825,0) 0(-3.175,0) 0(3.175,0) 0(16.825,0) 0(23.175,0)
  rect 0.3x1.45 smd: 1(-27.25,3.09) 2(-27.25,-3.09) 3(-26.75,3.09) 4(-26.75,-3.09) 5(-25.75,3.09) 6(-25.75,-3.09) 7(-25.25,3.09) 8(-25.25,-3.09) 9(-24.25,3.09) 10(-24.25,-3.09) 11(-23.75,3.09) 12(-23.75,-3.09) 13(-22.75,3.09) 14(-22.75,-3.09) 15(-22.25,3.09) 16(-22.25,-3.09) 17(-21.25,3.09) 18(-21.25,-3.09) 19(-20.75,3.09) 20(-20.75,-3.09) 21(-19.75,3.09) 22(-19.75,-3.09) 23(-19.25,3.09) 24(-19.25,-3.09) 25(-18.25,3.09) 26(-18.25,-3.09) 27(-17.75,3.09) 28(-17.75,-3.09) 29(-16.75,3.09) 30(-16.75,-3.09) 31(-16.25,3.09) 32(-16.25,-3.09) 33(-15.25,3.09) 34(-15.25,-3.09) 35(-14.75,3.09) 36(-14.75,-3.09) 37(-13.75,3.09) 38(-13.75,-3.09) 39(-13.25,3.09) 40(-13.25,-3.09) 41(-7.25,3.09) 42(-7.25,-3.09) 43(-6.75,3.09) 44(-6.75,-3.09) 45(-5.75,3.09) 46(-5.75,-3.09) 47(-5.25,3.09) 48(-5.25,-3.09) 49(-4.25,3.09) 50(-4.25,-3.09) 51(-3.75,3.09) 52(-3.75,-3.09) 53(-2.75,3.09) 54(-2.75,-3.09) 55(-2.25,3.09) 56(-2.25,-3.09) 57(-1.25,3.09) 58(-1.25,-3.09) 59(-0.75,3.09) 60(-0.75,-3.09) 61(0.25,3.09) 62(0.25,-3.09) 63(0.75,3.09) 64(0.75,-3.09) 65(1.75,3.09) 66(1.75,-3.09) 67(2.25,3.09) 68(2.25,-3.09) 69(3.25,3.09) 70(3.25,-3.09) 71(3.75,3.09) 72(3.75,-3.09) 73(4.75,3.09) 74(4.75,-3.09) 75(5.25,3.09) 76(5.25,-3.09) 77(6.25,3.09) 78(6.25,-3.09) 79(6.75,3.09) 80(6.75,-3.09) 81(12.75,3.09) 82(12.75,-3.09) 83(13.25,3.09) 84(13.25,-3.09) 85(14.25,3.09) 86(14.25,-3.09) 87(14.75,3.09) 88(14.75,-3.09) 89(15.75,3.09) 90(15.75,-3.09) 91(16.25,3.09) 92(16.25,-3.09) 93(17.25,3.09) 94(17.25,-3.09) 95(17.75,3.09) 96(17.75,-3.09) 97(18.75,3.09) 98(18.75,-3.09) 99(19.25,3.09) 100(19.25,-3.09) 101(20.25,3.09) 102(20.25,-3.09) 103(20.75,3.09) 104(20.75,-3.09) 105(21.75,3.09) 106(21.75,-3.09) 107(22.25,3.09) 108(22.25,-3.09) 109(23.25,3.09) 110(23.25,-3.09) 111(23.75,3.09) 112(23.75,-3.09) 113(24.75,3.09) 114(24.75,-3.09) 115(25.25,3.09) 116(25.25,-3.09) 117(26.25,3.09) 118(26.25,-3.09) 119(26.75,3.09) 120(26.75,-3.09)
  round 1.02 hole 1.02 unplated: MH(-29.24,2.03) MH(29.24,2.03)
  silkscreen extent -30.05,-3.05 30.05,3.05
QTH-090-01-X-D [mm]
  rect 2.54x0.64 smd: 0(-28.445,0) 0(-11.555,0) 0(-8.445,0) 0(8.445,0) 0(11.555,0) 0(28.445,0)
  rect 4.7x0.64 smd: 0(-23.175,0) 0(-16.825,0) 0(-3.175,0) 0(3.175,0) 0(16.825,0) 0(23.175,0)
  rect 0.3x1.45 smd: 1(-27.25,3.09) 2(-27.25,-3.09) 3(-26.75,3.09) 4(-26.75,-3.09) 5(-26.25,3.09) 6(-26.25,-3.09) 7(-25.75,3.09) 8(-25.75,-3.09) 9(-25.25,3.09) 10(-25.25,-3.09) 11(-24.75,3.09) 12(-24.75,-3.09) 13(-24.25,3.09) 14(-24.25,-3.09) 15(-23.75,3.09) 16(-23.75,-3.09) 17(-23.25,3.09) 18(-23.25,-3.09) 19(-22.75,3.09) 20(-22.75,-3.09) 21(-22.25,3.09) 22(-22.25,-3.09) 23(-21.75,3.09) 24(-21.75,-3.09) 25(-21.25,3.09) 26(-21.25,-3.09) 27(-20.75,3.09) 28(-20.75,-3.09) 29(-20.25,3.09) 30(-20.25,-3.09) 31(-19.75,3.09) 32(-19.75,-3.09) 33(-19.25,3.09) 34(-19.25,-3.09) 35(-18.75,3.09) 36(-18.75,-3.09) 37(-18.25,3.09) 38(-18.25,-3.09) 39(-17.75,3.09) 40(-17.75,-3.09) 41(-17.25,3.09) 42(-17.25,-3.09) 43(-16.75,3.09) 44(-16.75,-3.09) 45(-16.25,3.09) 46(-16.25,-3.09) 47(-15.75,3.09) 48(-15.75,-3.09) 49(-15.25,3.09) 50(-15.25,-3.09) 51(-14.75,3.09) 52(-14.75,-3.09) 53(-14.25,3.09) 54(-14.25,-3.09) 55(-13.75,3.09) 56(-13.75,-3.09) 57(-13.25,3.09) 58(-13.25,-3.09) 59(-12.75,3.09) 60(-12.75,-3.09) 61(-7.25,3.09) 62(-7.25,-3.09) 63(-6.75,3.09) 64(-6.75,-3.09) 65(-6.25,3.09) 66(-6.25,-3.09) 67(-5.75,3.09) 68(-5.75,-3.09) 69(-5.25,3.09) 70(-5.25,-3.09) 71(-4.75,3.09) 72(-4.75,-3.09) 73(-4.25,3.09) 74(-4.25,-3.09) 75(-3.75,3.09) 76(-3.75,-3.09) 77(-3.25,3.09) 78(-3.25,-3.09) 79(-2.75,3.09) 80(-2.75,-3.09) 81(-2.25,3.09) 82(-2.25,-3.09) 83(-1.75,3.09) 84(-1.75,-3.09) 85(-1.25,3.09) 86(-1.25,-3.09) 87(-0.75,3.09) 88(-0.75,-3.09) 89(-0.25,3.09) 90(-0.25,-3.09) 91(0.25,3.09) 92(0.25,-3.09) 93(0.75,3.09) 94(0.75,-3.09) 95(1.25,3.09) 96(1.25,-3.09) 97(1.75,3.09) 98(1.75,-3.09) 99(2.25,3.09) 100(2.25,-3.09) 101(2.75,3.09) 102(2.75,-3.09) 103(3.25,3.09) 104(3.25,-3.09) 105(3.75,3.09) 106(3.75,-3.09) 107(4.25,3.09) 108(4.25,-3.09) 109(4.75,3.09) 110(4.75,-3.09) 111(5.25,3.09) 112(5.25,-3.09) 113(5.75,3.09) 114(5.75,-3.09) 115(6.25,3.09) 116(6.25,-3.09) 117(6.75,3.09) 118(6.75,-3.09) 119(7.25,3.09) 120(7.25,-3.09) 121(12.75,3.09) 122(12.75,-3.09) 123(13.25,3.09) 124(13.25,-3.09) 125(13.75,3.09) 126(13.75,-3.09) 127(14.25,3.09) 128(14.25,-3.09) 129(14.75,3.09) 130(14.75,-3.09) 131(15.25,3.09) 132(15.25,-3.09) 133(15.75,3.09) 134(15.75,-3.09) 135(16.25,3.09) 136(16.25,-3.09) 137(16.75,3.09) 138(16.75,-3.09) 139(17.25,3.09) 140(17.25,-3.09) 141(17.75,3.09) 142(17.75,-3.09) 143(18.25,3.09) 144(18.25,-3.09) 145(18.75,3.09) 146(18.75,-3.09) 147(19.25,3.09) 148(19.25,-3.09) 149(19.75,3.09) 150(19.75,-3.09) 151(20.25,3.09) 152(20.25,-3.09) 153(20.75,3.09) 154(20.75,-3.09) 155(21.25,3.09) 156(21.25,-3.09) 157(21.75,3.09) 158(21.75,-3.09) 159(22.25,3.09) 160(22.25,-3.09) 161(22.75,3.09) 162(22.75,-3.09) 163(23.25,3.09) 164(23.25,-3.09) 165(23.75,3.09) 166(23.75,-3.09) 167(24.25,3.09) 168(24.25,-3.09) 169(24.75,3.09) 170(24.75,-3.09) 171(25.25,3.09) 172(25.25,-3.09) 173(25.75,3.09) 174(25.75,-3.09) 175(26.25,3.09) 176(26.25,-3.09) 177(26.75,3.09) 178(26.75,-3.09) 179(27.25,3.09) 180(27.25,-3.09)
  round 1.02 hole 1.02 unplated: MH(-29.24,2.03) MH(29.24,2.03)
  silkscreen extent -30.05,-3.05 30.05,3.05
RESC1005X06A#1 [mm] "Chip Resistor, 2-Leads, Body 1.00x0.50mm, OK custom footprint"
  rect 0.5x0.6 smd mask+0.051: 1(-0.5,0) 2(0.5,0)
RESC1005X06A#2 [mm] "Chip Resistor, 2-Leads, Body 1.00x0.50mm, OK custom footprint"
  rect 0.5x0.6 smd: 1(-0.5,0) 2(0.5,0)
RESC1608N [mm] "Chip Resistor, Body 1.6x0.8mm, IPC Medium Density"
  rect 0.9x1 smd: 1(-0.85,0) 2(0.85,0)
  silkscreen extent -0.14,-0.68 0.14,0.68, body extent -0.85,-0.48 0.85,0.48, height 0.6
RESC2012N [mm] "Chip Resistor, Body 2.0x1.3mm, IPC Medium Density"
  rect 1.2x1.4 smd: 1(-0.9,0) 2(0.9,0)
  body extent -1.07,-0.7 1.07,0.7, height 0.65
Si5338 [mm]
  rrect50% 0.8x0.25 smd: 1(-1.95,1.25) 2(-1.95,0.75) 3(-1.95,0.25) 4(-1.95,-0.25) 5(-1.95,-0.75) 6(-1.95,-1.25) 13(1.95,-1.25) 14(1.95,-0.75) 15(1.95,-0.25) 16(1.95,0.25) 17(1.95,0.75) 18(1.95,1.25)
  rrect50% 0.25x0.8 smd: 7(-1.25,-1.95) 8(-0.75,-1.95) 9(-0.25,-1.95) 10(0.25,-1.95) 11(0.75,-1.95) 12(1.25,-1.95) 19(1.25,1.95) 20(0.75,1.95) 21(0.25,1.95) 22(-0.25,1.95) 23(-0.75,1.95) 24(-1.25,1.95)
  rect 2.55x2.55 smd paste-10: PAD(0,0)
  silkscreen extent -2.55,-2.17 2.17,2.55, body extent -2.07,-2.07 2.07,2.07, height 0.8
SO-G8 [mm] "Small Outline; 8 Leads; Body Width 3.9 mm; Pitch 1.27 mm"
  rect 0.6x2.2 smd: 1(-1.905,-2.6) 2(-0.635,-2.6) 3(0.635,-2.6) 4(1.905,-2.6) 5(1.905,2.6) 6(0.635,2.6) 7(-0.635,2.6) 8(-1.905,2.6)
  silkscreen extent -2.45,-1.24 2.45,1.24
SOD-123 [mm] "SMT Diode Package from ON Semi"
  rect 0.91x1.22 smd: 1(-1.64,0) 2(1.64,0)
  silkscreen extent -0.92,-0.79 0.92,0.79
SOT23-6 [mm] "SOT-23; 6 Leads; Body 3.05 x 1.75 mm, inc. leads (LxW max)"
  rect 0.6x1.05 smd: 1(-0.95,-1.35) 2(0,-1.35) 3(0.95,-1.35) 4(0.95,1.35) 5(0,1.35) 6(-0.95,1.35)
  silkscreen extent -1.5,-0.56 1.5,0.56
SOT23-95P240X110 [mm] "SOT-23; 3 Leads; Body 3.0 x 2.6 mm, inc. leads (LxW max)"
  rect 0.8x0.9 smd: 1(-0.95,-1) 2(0.95,-1) 3(0,1)
  silkscreen extent -1.53,-0.29 1.54,0.77
SOT363-6N [mm] "SOT363, 6-Leads, Body 2x1.3mm, Pitch 0.65mm, Lead Span 2.1mm, IPC Medium Density"
  rect 0.85x0.4 smd: 1(-0.95,0.65) 2(-0.95,0) 3(-0.95,-0.65) 4(0.95,-0.65) 5(0.95,0) 6(0.95,0.65)
  silkscreen extent -0.26,-1.09 0.26,1.09, body extent -0.63,-1 0.63,1, height 1
TP-PTH-25/45 [mil] "Test point, plated through-hole, 25/45mil"
  round 45 hole 25: 1(0,0)
TP-SMD20 [mil] "Test point, surface-mount, 20mil"
  round 20 smd paste-78.74: 1(0,0)
TP-SMD40 [mm] "Test point, surface-mount, 40mil"
  round 1 smd paste-2: 1(0,0)
TPD8S009DSMR [mm]
  rect 0.3x1.45 smd: 1(-2.75,-0.925) 2(-2.25,-0.925) 3(-1.75,-0.925) 4(-1.25,-0.925) 5(-0.75,-0.925) 6(-0.25,-0.925) 7(0.25,-0.925) 8(0.75,-0.925) 9(1.25,-0.925) 10(1.75,-0.925) 11(2.25,-0.925) 12(2.75,-0.925) 13(1.5,0.925) 14(0,0.925) 15(-1.5,0.925)
  silkscreen extent -3.3,-1.3 3.3,1.3
USB4120-03-C [mm]
  rect 0.3x0.87 smd: A1(-2.75,0.865) A4(-1.25,0.865) A5(-0.75,0.865) A6(-0.25,0.865) A7(0.25,0.865) A8(0.75,0.865) A9(1.25,0.865) A12(2.75,0.865) B1(2.75,-0.865) B4(1.25,-0.865) B5(0.75,-0.865) B6(0.25,-0.865) B7(-0.25,-0.865) B8(-0.75,-0.865) B9(-1.25,-0.865) B12(-2.75,-0.865)
  oval 1.35x1.1 hole 0.6 slot 0.85 at 0 deg: M1(-2.4,2.15) M2(2.4,2.15) M3(2.4,-2.15) M4(-2.4,-2.15)
  round 0.52 hole 0.52 unplated paste-2539.97: M5(-3.75,0)
  oval 0.72x0.52 hole 0.52 slot 0.72 at 0 deg unplated paste-2539.97: M6(3.75,0)
  silkscreen extent -4.67,-1.8 4.67,1.8
VLS4012CX [mm]
  rect 1.3x4 smd: 1(-1.35,0) 2(1.35,0)
  silkscreen extent -0.44,-2.2 0.44,2.2
WQFN-30 [mm]
  rect 0.1x0.1 smd: 1(-1.2,1.8) 10(-1.2,-1.8) 11(-0.8,-2.2) 15(0.8,-2.2) 16(1.2,-1.8) 25(1.2,1.8) 26(0.8,2.2) 30(-0.8,2.2)
  rect 0.5x0.2 smd: 2(-1.2,1.4) 3(-1.2,1) 4(-1.2,0.6) 5(-1.2,0.2) 6(-1.2,-0.2) 7(-1.2,-0.6) 8(-1.2,-1) 9(-1.2,-1.4) 17(1.2,-1.4) 18(1.2,-1) 19(1.2,-0.6) 20(1.2,-0.2) 21(1.2,0.2) 22(1.2,0.6) 23(1.2,1) 24(1.2,1.4)
  rect 0.2x0.5 smd: 12(-0.4,-2.2) 13(0,-2.2) 14(0.4,-2.2) 27(0.4,2.2) 28(0,2.2) 29(-0.4,2.2)
  rect 1.2x3.2 smd: PAD(0.015,0.02)
  L1-TOP region: -1.45,1.9 -1.45,1.7 -0.95,1.7 -0.95,1.81 -1.04,1.9
  L1-TOP region: -0.9,2.45 -0.7,2.45 -0.7,1.95 -0.81,1.95 -0.9,2.04
  L1-TOP region: -0.9,-2.45 -0.7,-2.45 -0.7,-1.95 -0.81,-1.95 -0.9,-2.04
  L1-TOP region: 1.45,-1.9 1.45,-1.7 0.95,-1.7 0.95,-1.81 1.04,-1.9
  L1-TOP region: 0.9,2.45 0.7,2.45 0.7,1.95 0.81,1.95 0.9,2.04
  L1-TOP region: -1.45,-1.9 -1.45,-1.7 -0.95,-1.7 -0.95,-1.81 -1.04,-1.9
  L1-TOP region: 0.9,-2.45 0.7,-2.45 0.7,-1.95 0.81,-1.95 0.9,-2.04
  L1-TOP region: 1.45,1.9 1.45,1.7 0.95,1.7 0.95,1.81 1.04,1.9
  silkscreen extent -1.3,-2.32 1.3,2.32
XAL60XX [mm]
  rect 1.43x5.5 smd: 1(-2.02,0) 2(2.02,0)
  silkscreen extent -3.25,-3.35 3.25,3.35
XILINX-JTAG [mm] "2mm 2x7 header"
  rect 1.3x1.3 hole 0.8: 1(-6,-1)
  round 1.3 hole 0.8: 2(-6,1) 3(-4,-1) 4(-4,1) 5(-2,-1) 6(-2,1) 7(0,-1) 8(0,1) 9(2,-1) 10(2,1) 11(4,-1) 12(4,1) 13(6,-1) 14(6,1)
  silkscreen extent -8.32,-3.15 8.32,3.15

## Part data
*1: library part OKLOGO, partnumber=ALIGNI_IGNORE
C1 C36 C170 C171 C182 C183 C185 C187 C189: library part 000070, Manufacturer=Kemet, Manufacturer_PN=C0402C104K8PACTU, ValueFloat=1E-7, x_tolerance=10
C2 C69 C70 C71 C72 C74 C94: library part 000070, "Ceramic capacitor", Manufacturer=Kemet, ValueFloat=1E-7, Voltage=10V, x_tolerance=10
C3 C4 C5 C6 C7 C8: library part 000070, Manufacturer=Kemet, ValueFloat=1E-7, x_tolerance=10
C9 C13 C19 C23: library part 000824, "Ceramic capacitor", Manufacturer="Taiyo Yuden", Tolerance (%)=20, ValueFloat=4.7E-6
C10 C11 C12 C14 C15 C16 C17 C22 C28 C29 C30 C31 C32 C33 C34 C39 C40 C41: library part 000070, Manufacturer=Kemet, Tolerance (%)=10, ValueFloat=1E-7
C18 C35 C83 C84 C87 C88 C100: library part 000295, "Ceramic Capacitor", Manufacturer=Kemet, Tolerance (%)=10, ValueFloat=1E-8
C20 C21: library part 001073, "Ceramic capacitor", Manufacturer="Taiyo Yuden", ValueFloat=1E-7, Voltage=25V, x_tolerance=10
C24 C25 C26 C27 C52 C53 C55 C57 C68 C178 C180 C184: library part 000070, Manufacturer=Kemet, Manufacturer_PN=C0402C104K8PACTU, ValueFloat=1E-7, Voltage=10V, x_tolerance=10
C37 C38: library part 001640, "Ceramic capacitor", Manufacturer=Kemet, Tolerance (%)=5, ValueFloat=1.8E-11, Voltage=50
C42: library part 000824, Manufacturer="Taiyo Yuden", ValueFloat=4.7E-6, x_tolerance=20
C49 C50 C65 C66: library part 001073, Manufacturer=Kemet, partnumber=000070, ValueFloat=1E-7, Voltage=10V, x_tolerance=10
C51 C54 C56 C58 C67 C179 C181 C186: library part 001284, Manufacturer="Taiyo Yuden", Manufacturer_PN=LMK316AB7226KL-TR, ValueFloat=2.2E-5, Voltage=10V, x_temperature_characteristic=X7R, x_tolerance=10
C59 C60 C62 C63 C75 C76 C79 C80 C81 C118 C119 C126 C129 C139 C142 C149 C150 C174 C175 C188 C212 C218 C219: library part 000070, Manufacturer=Kemet, ValueFloat=1E-7, Voltage=10V, x_tolerance=10
C61 C64 C213: library part 000480, Manufacturer="Taiyo Yuden", ValueFloat=1E-6, Voltage=10V, x_tolerance=10
C73: library part 001791, "Ceramic Capacitor", Manufacturer="Samsung Electro-Mechanics", Tolerance (%)=10, ValueFloat=2.2E-6, Voltage=6.3V
C77 C78: library part 000808, "Ceramic capacitor", Manufacturer=Kemet, ValueFloat=1.2E-11, Voltage=50V, x_tolerance=5
C82 C85 C86 C89 C99: library part 001786, "Ceramic capacitor", Manufacturer="Taiyo Yuden", Tolerance (%)=10, ValueFloat=1E-5
C90 C92 C95 C97 C101 C104 C105 C108 C109: library part 000480, "Ceramic capacitor", Manufacturer="Taiyo Yuden", Tolerance (%)=10, ValueFloat=1E-6
C91 C93 C96 C98 C102 C103 C106 C107 C110: library part 000070, "Ceramic capacitor", Manufacturer=Kemet, Tolerance (%)=10, ValueFloat=1E-7
C111 C112 C159 C163: library part 001073, "Ceramic capacitor", Manufacturer="Taiyo Yuden", Tolerance (%)=10, ValueFloat=1E-7
C113 C220: library part 001346, Manufacturer="Taiyo Yuden", ValueFloat=1E-5, Voltage=10V, x_tolerance=20
C114: library part 000824, Manufacturer="Taiyo Yuden", ValueFloat=4.7E-6, Voltage=6.3V, x_tolerance=20
C115: library part 001926, Manufacturer=TDK, ValueFloat=3.3E-6, Voltage=10V, x_tolerance=20
C116 C127 C140: library part 001172, "Ceramic Capacitor", Manufacturer=TDK, Tolerance (%)=20, ValueFloat=2.2E-5, Voltage=35V, x_voltage-rating=35
C117 C128 C141: library part 001073, "Ceramic capacitor", Manufacturer="Taiyo Yuden", Tolerance (%)=10, ValueFloat=1E-7, Voltage=25V
C120 C121 C130 C131 C143 C144 C151 C152: library part 001284, "Ceramic capacitor", Manufacturer="Taiyo Yuden", Tolerance (%)=10, ValueFloat=2.2E-5, Voltage=10V
C122 C133: library part 001004, Manufacturer=Kemet, Manufacturer_PN=C0402C560J5GACTU, ValueFloat=5.6E-11, Voltage=50V, x_temperature_characteristic=C0G, x_tolerance=5
C123 C136 C155: library part 000930, "Ceramic capacitor", Manufacturer=Kemet, Tolerance (%)=10, ValueFloat=4.7E-9, Voltage=50V
C124 C132 C138 C146: library part 000070, "Ceramic capacitor", Manufacturer=Kemet, Tolerance (%)=10, ValueFloat=1E-7, Voltage=10V
C125 C137 C148 C157: library part 000807, "Ceramic capacitor", Manufacturer=Kemet, Tolerance (%)=5, ValueFloat=2.2E-11, Voltage=50V
C134: library part 001532, "Polarized", Manufacturer=Panasonic, ValueFloat=0.00022, Voltage=25V, x_tolerance=20, x_voltage-rating=25
C135: library part 001073, Manufacturer="Taiyo Yuden", ValueFloat=1E-7, Voltage=25V, x_tolerance=10
C145 C153: library part 001004, "Ceramic capacitor", Manufacturer=Kemet, Tolerance (%)=5, ValueFloat=5.6E-11, Voltage=50V
C147: library part 000930, Manufacturer=Kemet, ValueFloat=4.7E-9, Voltage=50V, x_tolerance=10
C154: library part 000400, Manufacturer=Kemet, Manufacturer_PN=C0402C101J5GACTU, ValueFloat=1E-10, Voltage=50V
C156: library part 000962, "Ceramic capacitor", Manufacturer=Murata, Tolerance (%)=3.125, ValueFloat=5E-12, Voltage=50V
C164: library part 002158, "Ceramic capacitor High Voltage", Manufacturer=Murata, Tolerance (%)=10, ValueFloat=4.7E-9, Voltage=2000
C168 C214: library part 000935, "Ceramic capacitor", Manufacturer=Kemet, Tolerance (%)=5, ValueFloat=3.3E-11, Voltage=50
C190: library part 000295, Manufacturer=Kemet, ValueFloat=1E-8, x_tolerance=10
C215: library part 000491, "Ceramic capacitor", Manufacturer="Taiyo Yuden", ValueFloat=1E-5, Voltage=10V, x_tolerance=10
C221: library part 001785, "Ceramic Capacitor", Manufacturer=Murata, Tolerance (%)=20, ValueFloat=0.00015, Voltage=6.3V
D1: library part 001432, "LED", Manufacturer=Dialight, Manufacturer_PN=598-8010-107F
D2 D3: library part 001302, "Default Diode", Manufacturer="Micro Commercial Co", Manufacturer_PN=1N4148W-TP
D4: library part 001433, "LED", Manufacturer=Dialight, Manufacturer_PN=598-8070-107F
D5: library part 002405, "4 channel TVS diode array", Manufacturer="Diodes Incorporated"
FB1 FB5: library part 000783, "Ferrite Chip", Manufacturer=Murata, ValueFloat=220
FB2 FB3 FB4: library part 000569, "Ferrite bead", Manufacturer=Steward, ValueFloat=600
FID1 FID2 FID3 FID4 FID5 FID6 FID7 FID8: "PCB fiducial", partnumber=ALIGNI_IGNORE
J1 J8 J9 J11: library part 001604, "0.8mm hi-speed, high-density header (male)", Manufacturer=Samtec
J2: library part 000541, "2mm header, shrouded", Manufacturer=Molex
J3: library part 000583, Manufacturer=Molex
J4: library part 001338, Manufacturer=Molex
J5 J6 J7: library part 000694, "0.5mm hi-speed, high-density socket (male)", Manufacturer=Samtec
J10: library part 001938, "2mm header, 6x2, thru-hole", Manufacturer=Molex
J12: library part 000988, "SATA 7-pin receptacle", Manufacturer=Molex
J13: library part 001173, Manufacturer="Sullins Electronics Corp."
J14 J15: library part 001782, Manufacturer=Amphenol
J16: library part 001907, Manufacturer=Molex
J17: library part 001517, "RJ-45", Manufacturer="Bel Fuse, Inc."
J18: library part 000356, Manufacturer="CUI Inc."
J19: library part 001950, Manufacturer=Molex
J20: library part 001943, "DisplayPort, full-size, right-angle", Manufacturer=Molex
J21: library part 002404, "USB 2.0 Type-C receptacle vertical-mount", Manufacturer=GCT
JSO1 JSO2 JSO3 JSO4: library part 001879, "Jack screw standoff, 5mm board stack height", Manufacturer=Samtec, Manufacturer_PN=JSO-0515-01
L1 L2: library part 001543, "Power inductor, 2.2uH, 7A, 12.7mOhm", Manufacturer=Coilcraft, Tolerance (%)=20, ValueFloat=2.2E-6
L3 L4: library part 002384, Manufacturer=TDK, ValueFloat=2.2E-6, x_tolerance=20
L5 L6 L7 L8 L9 L10: library part 002331, "Thin Film, 1uH, 3.1A, 50mOhm, Unshielded", Manufacturer="Samsung Electro-Mechanics", Tolerance (%)=20, ValueFloat=1E-6
MC1: library part 000855, "0.5mm Double Row High Speed Socket Assembly", Manufacturer=Samtec
MC2: library part 001769, Manufacturer=Samtec
MC3: library part 000876, "0.5mm Double Row High Speed Socket Assembly", Manufacturer=Samtec
MH1 MH2 MH3 MH4 MH5: "Mounting hole", partnumber=ALIGNI_IGNORE
Q1: library part 001237, "N-Channel MOSFET", Manufacturer="Fairchild Semiconductor", Manufacturer_PN=FDN337N, PackageDocument=1995/1996
Q2 Q3: library part 002018, Manufacturer=Vishay
QSFP1 QSFP2: library part 001781, Manufacturer=Amphenol, Manufacturer_PN=U95-T111-1001
R1: library part 001551, Manufacturer=Vishay, ValueFloat=34000, x_tolerance=1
